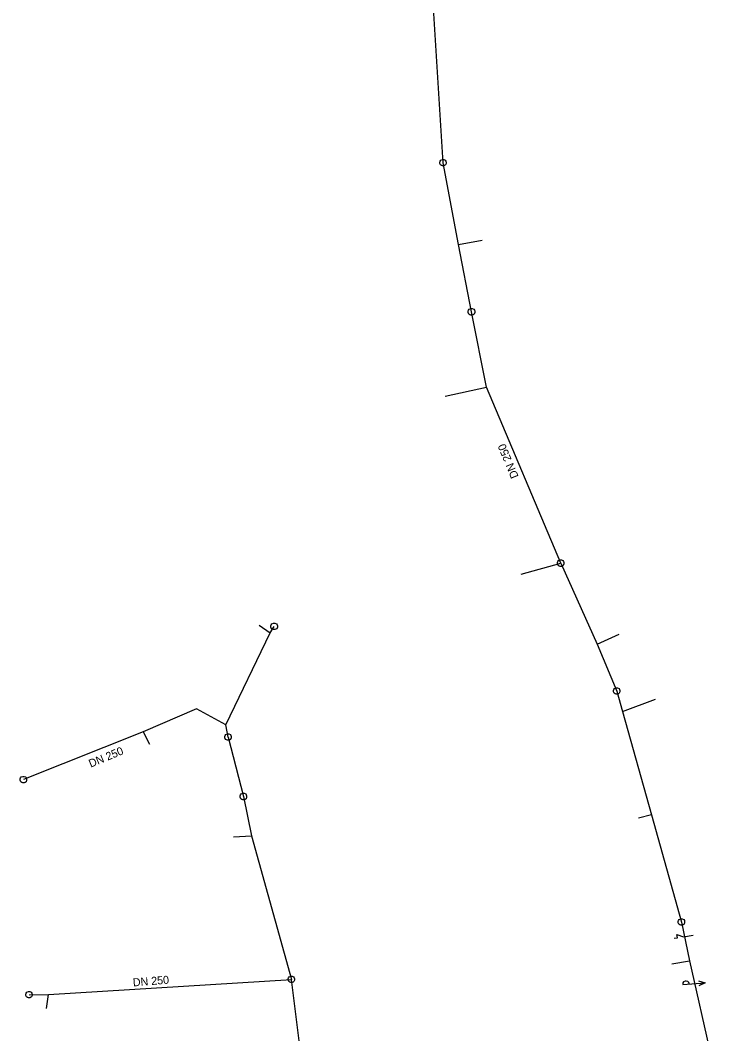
# Model space of a CAD drawing. Extents: x -717256 to -716843, y -1145423 to -1142840.
# Drawn here: x -717115.6 to -717004.5, y -1143346.8 to -1143188.5 of the extents above; entities that cross this region are included whole.
import ezdxf

# ---------------------------------------------------------------- set-up
doc = ezdxf.new("R2010")
doc.units = 0
for name, color, linetype in [('Vrstva 30', 7, 'Continuous'), ('Vrstva 31', 7, 'Continuous'), ('Vrstva 9', 7, 'Continuous')]:
    doc.layers.add(name, color=color, linetype=linetype)

msp = doc.modelspace()

# ---------------------------------------------------------------- linework, layer by layer
at = {"layer": 'Vrstva 30'}
for p, q in [((-717049.52, -1143210.751), (-717051.345, -1143181.336)), ((-717050.02, -1143210.651), (-717049.97, -1143210.501)), ((-717050.02, -1143210.851), (-717050.02, -1143210.651)), ((-717049.92, -1143211.101), (-717050.02, -1143210.851)), ((-717049.97, -1143210.501), (-717049.87, -1143210.351)), ((-717049.77, -1143211.201), (-717049.92, -1143211.101)), ((-717049.87, -1143210.351), (-717049.62, -1143210.251)), ((-717049.62, -1143210.251), (-717049.42, -1143210.251)), ((-717047.084, -1143223.512), (-717049.52, -1143210.751)), ((-717049.42, -1143210.251), (-717049.17, -1143210.351)), ((-717049.12, -1143211.101), (-717049.27, -1143211.201)), ((-717049.17, -1143210.351), (-717049.07, -1143210.501)), ((-717049.02, -1143210.851), (-717049.12, -1143211.101)), ((-717049.07, -1143210.501), (-717049.02, -1143210.651)), ((-717049.02, -1143210.651), (-717049.02, -1143210.851)), ((-717049.62, -1143211.251), (-717049.77, -1143211.201)), ((-717049.42, -1143211.251), (-717049.62, -1143211.251)), ((-717049.27, -1143211.201), (-717049.42, -1143211.251)), ((-717045.075, -1143234.043), (-717047.084, -1143223.512)), ((-717045.575, -1143233.943), (-717045.525, -1143233.793)), ((-717045.575, -1143234.143), (-717045.575, -1143233.943)), ((-717045.475, -1143234.393), (-717045.575, -1143234.143)), ((-717045.525, -1143233.793), (-717045.425, -1143233.643)), ((-717045.325, -1143234.493), (-717045.475, -1143234.393)), ((-717045.425, -1143233.643), (-717045.175, -1143233.543)), ((-717045.175, -1143234.543), (-717045.325, -1143234.493)), ((-717045.175, -1143233.543), (-717044.975, -1143233.543)), ((-717044.975, -1143234.543), (-717045.175, -1143234.543)), ((-717042.74, -1143245.811), (-717045.075, -1143234.043)), ((-717044.975, -1143233.543), (-717044.725, -1143233.643)), ((-717044.825, -1143234.493), (-717044.975, -1143234.543)), ((-717044.675, -1143234.393), (-717044.825, -1143234.493)), ((-717044.725, -1143233.643), (-717044.625, -1143233.793)), ((-717044.575, -1143234.143), (-717044.675, -1143234.393)), ((-717044.625, -1143233.793), (-717044.575, -1143233.943)), ((-717044.575, -1143233.943), (-717044.575, -1143234.143)), ((-717031.116, -1143273.318), (-717042.74, -1143245.811)), ((-717031.566, -1143273.068), (-717031.466, -1143272.918)), ((-717031.466, -1143272.918), (-717031.216, -1143272.818)), ((-717031.216, -1143272.818), (-717031.016, -1143272.818)), ((-717031.016, -1143272.818), (-717030.766, -1143272.918)), ((-717030.766, -1143272.918), (-717030.666, -1143273.068)), ((-717037.281, -1143275.043), (-717031.116, -1143273.318)), ((-717031.616, -1143273.218), (-717031.566, -1143273.068)), ((-717031.616, -1143273.418), (-717031.616, -1143273.218)), ((-717031.516, -1143273.668), (-717031.616, -1143273.418)), ((-717031.366, -1143273.768), (-717031.516, -1143273.668)), ((-717031.216, -1143273.818), (-717031.366, -1143273.768)), ((-717031.016, -1143273.818), (-717031.216, -1143273.818)), ((-717031.116, -1143273.318), (-717025.416, -1143285.966)), ((-717030.866, -1143273.768), (-717031.016, -1143273.818)), ((-717030.716, -1143273.668), (-717030.866, -1143273.768)), ((-717030.616, -1143273.418), (-717030.716, -1143273.668)), ((-717030.666, -1143273.068), (-717030.616, -1143273.218)), ((-717030.616, -1143273.218), (-717030.616, -1143273.418)), ((-717076.579, -1143284.216), (-717075.933, -1143283.206)), ((-717076.433, -1143283.106), (-717076.383, -1143282.956)), ((-717076.433, -1143283.306), (-717076.433, -1143283.106)), ((-717076.333, -1143283.556), (-717076.433, -1143283.306)), ((-717076.383, -1143282.956), (-717076.283, -1143282.806)), ((-717076.183, -1143283.656), (-717076.333, -1143283.556)), ((-717076.283, -1143282.806), (-717076.033, -1143282.706)), ((-717076.033, -1143283.706), (-717076.183, -1143283.656)), ((-717076.033, -1143282.706), (-717075.833, -1143282.706)), ((-717075.833, -1143283.706), (-717076.033, -1143283.706)), ((-717075.833, -1143282.706), (-717075.583, -1143282.806)), ((-717075.683, -1143283.656), (-717075.833, -1143283.706)), ((-717075.533, -1143283.556), (-717075.683, -1143283.656)), ((-717075.583, -1143282.806), (-717075.483, -1143282.956)), ((-717075.433, -1143283.306), (-717075.533, -1143283.556)), ((-717075.483, -1143282.956), (-717075.433, -1143283.106)), ((-717075.433, -1143283.106), (-717075.433, -1143283.306)), ((-717083.473, -1143298.554), (-717076.579, -1143284.216)), ((-717025.416, -1143285.966), (-717022.357, -1143293.297)), ((-717022.857, -1143293.197), (-717022.807, -1143293.047)), ((-717022.857, -1143293.397), (-717022.857, -1143293.197)), ((-717022.757, -1143293.647), (-717022.857, -1143293.397)), ((-717022.807, -1143293.047), (-717022.707, -1143292.897)), ((-717022.707, -1143292.897), (-717022.457, -1143292.797)), ((-717022.457, -1143292.797), (-717022.257, -1143292.797)), ((-717022.357, -1143293.297), (-717021.454, -1143296.516)), ((-717022.257, -1143292.797), (-717022.007, -1143292.897)), ((-717022.007, -1143292.897), (-717021.907, -1143293.047)), ((-717021.857, -1143293.397), (-717021.957, -1143293.647)), ((-717021.907, -1143293.047), (-717021.857, -1143293.197)), ((-717021.857, -1143293.197), (-717021.857, -1143293.397)), ((-717022.607, -1143293.747), (-717022.757, -1143293.647)), ((-717022.457, -1143293.797), (-717022.607, -1143293.747)), ((-717022.257, -1143293.797), (-717022.457, -1143293.797)), ((-717022.107, -1143293.747), (-717022.257, -1143293.797)), ((-717021.957, -1143293.647), (-717022.107, -1143293.747)), ((-717088.075, -1143296.057), (-717096.401, -1143299.698)), ((-717083.473, -1143298.554), (-717088.075, -1143296.057)), ((-717021.454, -1143296.516), (-717016.934, -1143312.641)), ((-717096.401, -1143299.698), (-717115.132, -1143307.128)), ((-717083.131, -1143300.498), (-717083.473, -1143298.554)), ((-717083.631, -1143300.398), (-717083.581, -1143300.248)), ((-717083.631, -1143300.598), (-717083.631, -1143300.398)), ((-717083.531, -1143300.848), (-717083.631, -1143300.598)), ((-717083.581, -1143300.248), (-717083.481, -1143300.098)), ((-717083.381, -1143300.948), (-717083.531, -1143300.848)), ((-717083.481, -1143300.098), (-717083.231, -1143299.998)), ((-717083.231, -1143300.998), (-717083.381, -1143300.948)), ((-717083.231, -1143299.998), (-717083.031, -1143299.998)), ((-717083.031, -1143300.998), (-717083.231, -1143300.998)), ((-717083.131, -1143300.498), (-717080.732, -1143309.781)), ((-717083.031, -1143299.998), (-717082.781, -1143300.098)), ((-717082.881, -1143300.948), (-717083.031, -1143300.998)), ((-717082.731, -1143300.848), (-717082.881, -1143300.948)), ((-717082.781, -1143300.098), (-717082.681, -1143300.248)), ((-717082.631, -1143300.598), (-717082.731, -1143300.848)), ((-717082.681, -1143300.248), (-717082.631, -1143300.398)), ((-717082.631, -1143300.398), (-717082.631, -1143300.598)), ((-717115.632, -1143307.028), (-717115.582, -1143306.878)), ((-717115.632, -1143307.228), (-717115.632, -1143307.028)), ((-717115.532, -1143307.478), (-717115.632, -1143307.228)), ((-717115.582, -1143306.878), (-717115.482, -1143306.728)), ((-717115.382, -1143307.578), (-717115.532, -1143307.478)), ((-717115.482, -1143306.728), (-717115.232, -1143306.628)), ((-717115.232, -1143307.628), (-717115.382, -1143307.578)), ((-717115.232, -1143306.628), (-717115.032, -1143306.628)), ((-717115.032, -1143307.628), (-717115.232, -1143307.628)), ((-717115.032, -1143306.628), (-717114.782, -1143306.728)), ((-717114.882, -1143307.578), (-717115.032, -1143307.628)), ((-717114.732, -1143307.478), (-717114.882, -1143307.578)), ((-717114.782, -1143306.728), (-717114.682, -1143306.878)), ((-717114.632, -1143307.228), (-717114.732, -1143307.478)), ((-717114.682, -1143306.878), (-717114.632, -1143307.028)), ((-717114.632, -1143307.028), (-717114.632, -1143307.228)), ((-717081.082, -1143309.381), (-717080.832, -1143309.281)), ((-717080.832, -1143309.281), (-717080.632, -1143309.281)), ((-717080.632, -1143309.281), (-717080.382, -1143309.381)), ((-717081.232, -1143309.681), (-717081.182, -1143309.531)), ((-717081.232, -1143309.881), (-717081.232, -1143309.681)), ((-717081.132, -1143310.131), (-717081.232, -1143309.881)), ((-717081.182, -1143309.531), (-717081.082, -1143309.381)), ((-717080.982, -1143310.231), (-717081.132, -1143310.131)), ((-717080.832, -1143310.281), (-717080.982, -1143310.231)), ((-717080.632, -1143310.281), (-717080.832, -1143310.281)), ((-717080.732, -1143309.781), (-717079.495, -1143315.921)), ((-717080.482, -1143310.231), (-717080.632, -1143310.281)), ((-717080.332, -1143310.131), (-717080.482, -1143310.231)), ((-717080.382, -1143309.381), (-717080.282, -1143309.531)), ((-717080.232, -1143309.881), (-717080.332, -1143310.131)), ((-717080.282, -1143309.531), (-717080.232, -1143309.681)), ((-717080.232, -1143309.681), (-717080.232, -1143309.881)), ((-717016.934, -1143312.641), (-717012.24, -1143329.39)), ((-717079.495, -1143315.921), (-717073.23, -1143338.352)), ((-717012.74, -1143329.29), (-717012.69, -1143329.14)), ((-717012.74, -1143329.49), (-717012.74, -1143329.29)), ((-717012.64, -1143329.74), (-717012.74, -1143329.49)), ((-717012.69, -1143329.14), (-717012.59, -1143328.99)), ((-717012.49, -1143329.84), (-717012.64, -1143329.74)), ((-717012.59, -1143328.99), (-717012.34, -1143328.89)), ((-717012.34, -1143329.89), (-717012.49, -1143329.84)), ((-717012.34, -1143328.89), (-717012.14, -1143328.89)), ((-717012.14, -1143329.89), (-717012.34, -1143329.89)), ((-717012.24, -1143329.39), (-717010.994, -1143335.446)), ((-717012.14, -1143328.89), (-717011.89, -1143328.99)), ((-717011.99, -1143329.84), (-717012.14, -1143329.89)), ((-717011.84, -1143329.74), (-717011.99, -1143329.84)), ((-717011.89, -1143328.99), (-717011.79, -1143329.14)), ((-717011.74, -1143329.49), (-717011.84, -1143329.74)), ((-717011.79, -1143329.14), (-717011.74, -1143329.29)), ((-717011.74, -1143329.29), (-717011.74, -1143329.49)), ((-717010.994, -1143335.446), (-717004.534, -1143363.907)), ((-717111.206, -1143340.717), (-717073.23, -1143338.352)), ((-717073.73, -1143338.252), (-717073.68, -1143338.102)), ((-717073.73, -1143338.452), (-717073.73, -1143338.252)), ((-717073.63, -1143338.702), (-717073.73, -1143338.452)), ((-717073.68, -1143338.102), (-717073.58, -1143337.952)), ((-717073.48, -1143338.802), (-717073.63, -1143338.702)), ((-717073.58, -1143337.952), (-717073.33, -1143337.852)), ((-717073.33, -1143338.852), (-717073.48, -1143338.802)), ((-717073.33, -1143337.852), (-717073.13, -1143337.852)), ((-717073.13, -1143338.852), (-717073.33, -1143338.852)), ((-717069.755, -1143365.449), (-717073.23, -1143338.352)), ((-717073.13, -1143337.852), (-717072.88, -1143337.952)), ((-717072.98, -1143338.802), (-717073.13, -1143338.852)), ((-717072.83, -1143338.702), (-717072.98, -1143338.802)), ((-717072.88, -1143337.952), (-717072.78, -1143338.102)), ((-717072.73, -1143338.452), (-717072.83, -1143338.702)), ((-717072.78, -1143338.102), (-717072.73, -1143338.252)), ((-717072.73, -1143338.252), (-717072.73, -1143338.452)), ((-717114.757, -1143340.647), (-717114.707, -1143340.497)), ((-717114.757, -1143340.847), (-717114.757, -1143340.647)), ((-717114.657, -1143341.097), (-717114.757, -1143340.847)), ((-717114.707, -1143340.497), (-717114.607, -1143340.347)), ((-717114.607, -1143340.347), (-717114.357, -1143340.247)), ((-717114.357, -1143340.247), (-717114.157, -1143340.247)), ((-717114.257, -1143340.747), (-717111.206, -1143340.717)), ((-717114.157, -1143340.247), (-717113.907, -1143340.347)), ((-717113.907, -1143340.347), (-717113.807, -1143340.497)), ((-717113.757, -1143340.847), (-717113.857, -1143341.097)), ((-717113.807, -1143340.497), (-717113.757, -1143340.647)), ((-717113.757, -1143340.647), (-717113.757, -1143340.847)), ((-717114.507, -1143341.197), (-717114.657, -1143341.097)), ((-717114.357, -1143341.247), (-717114.507, -1143341.197)), ((-717114.157, -1143341.247), (-717114.357, -1143341.247)), ((-717114.007, -1143341.197), (-717114.157, -1143341.247)), ((-717113.857, -1143341.097), (-717114.007, -1143341.197))]:
    msp.add_line(p, q, dxfattribs=at)
at = {"layer": 'Vrstva 31'}
for p, q in [((-717047.084, -1143223.512), (-717043.384, -1143222.826)), ((-717049.168, -1143247.25), (-717042.74, -1143245.811)), ((-717078.27, -1143282.992), (-717076.579, -1143284.216)), ((-717025.416, -1143285.966), (-717022.002, -1143284.42)), ((-717021.454, -1143296.516), (-717016.325, -1143294.542)), ((-717096.401, -1143299.698), (-717095.444, -1143301.625)), ((-717016.934, -1143312.641), (-717018.937, -1143313.147)), ((-717082.279, -1143316.081), (-717079.495, -1143315.921)), ((-717013.749, -1143335.928), (-717010.994, -1143335.446)), ((-717111.511, -1143342.884), (-717111.206, -1143340.717))]:
    msp.add_line(p, q, dxfattribs=at)
at = {"layer": 'Vrstva 9'}
for p, q in [((-717012.885, -1143331.841), (-717012.963, -1143331.347)), ((-717012.963, -1143331.347), (-717011.898, -1143331.685)), ((-717011.898, -1143331.685), (-717010.416, -1143331.45)), ((-717013.379, -1143331.919), (-717012.885, -1143331.841)), ((-717012.01, -1143338.897), (-717012.048, -1143339.05)), ((-717012.048, -1143339.05), (-717012.04, -1143339.15)), ((-717012.04, -1143339.15), (-717008.551, -1143338.875)), ((-717011.922, -1143338.739), (-717012.01, -1143338.897)), ((-717011.681, -1143338.62), (-717011.922, -1143338.739)), ((-717011.481, -1143338.604), (-717011.681, -1143338.62)), ((-717011.224, -1143338.684), (-717011.481, -1143338.604)), ((-717011.113, -1143338.826), (-717011.224, -1143338.684)), ((-717011.051, -1143338.972), (-717011.113, -1143338.826)), ((-717011.043, -1143339.071), (-717011.051, -1143338.972)), ((-717009.579, -1143338.555), (-717008.551, -1143338.875)), ((-717008.551, -1143338.875), (-717009.516, -1143339.352))]:
    msp.add_line(p, q, dxfattribs=at)

# ---------------------------------------------------------------- texts
at = {"layer": 'Vrstva 30'}
for rotation, p in [(112.5, (-717037.681, -1143259.77)), (22.5, (-717104.612, -1143305.277)), (4.5, (-717097.979, -1143339.454))]:
    msp.add_text('DN 250', height=1.25, rotation=rotation, dxfattribs=at).set_placement(p)

doc.saveas('drawing.dxf')
